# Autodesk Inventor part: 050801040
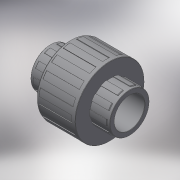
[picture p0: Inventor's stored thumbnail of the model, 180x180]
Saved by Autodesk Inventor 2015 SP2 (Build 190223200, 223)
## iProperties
Created: 2017-10
Part Number: 050801040
Material: Generic
Description: PLASSON THR.UNION+O RING PVC 4"
Document SubType Name: Modeling
Designer: KIM
Density: 1 g/cm^3
Appearance: Default
Author: KIM
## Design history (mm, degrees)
derived "050801.ipt"
feature "Solid1::050801.ipt"
tag "TaggingFeature1"
body "Solid1"
other parameters: "d0" = 145, "d3" = 110.072, "d4" = 110.072, "d5" = 126.5828, "d6" = 122.78532, "d7" = 126.5828, "d8" = 151, "d10" = 41, "d11" = 99.0648, "d14" = 30.75, "d17" = 4.1, "d19" = 147.98, "d20" = 4.1, "d21" = 2.265, "d25" = 15.1, "d26" = 7.55, "d27" = 71.46, "d28" = 0, "d32" = 15.1, "d33" = 7.55, "d35" = 0, "d39" = 0.16, "d45" = 1.89874, "d49" = 360 deg, "d51" = 1.51, "d55" = 360 deg, "d57" = 41, "d58" = 30.75, "d_" = 16, "E_" = 151, "H_" = 145, "l_" = 14, "lt_" = 41, "Z_" = 11, "G_" = 110.072, "d24" = 79.4, "d40" = 1.89874, "d44" = 1.51
